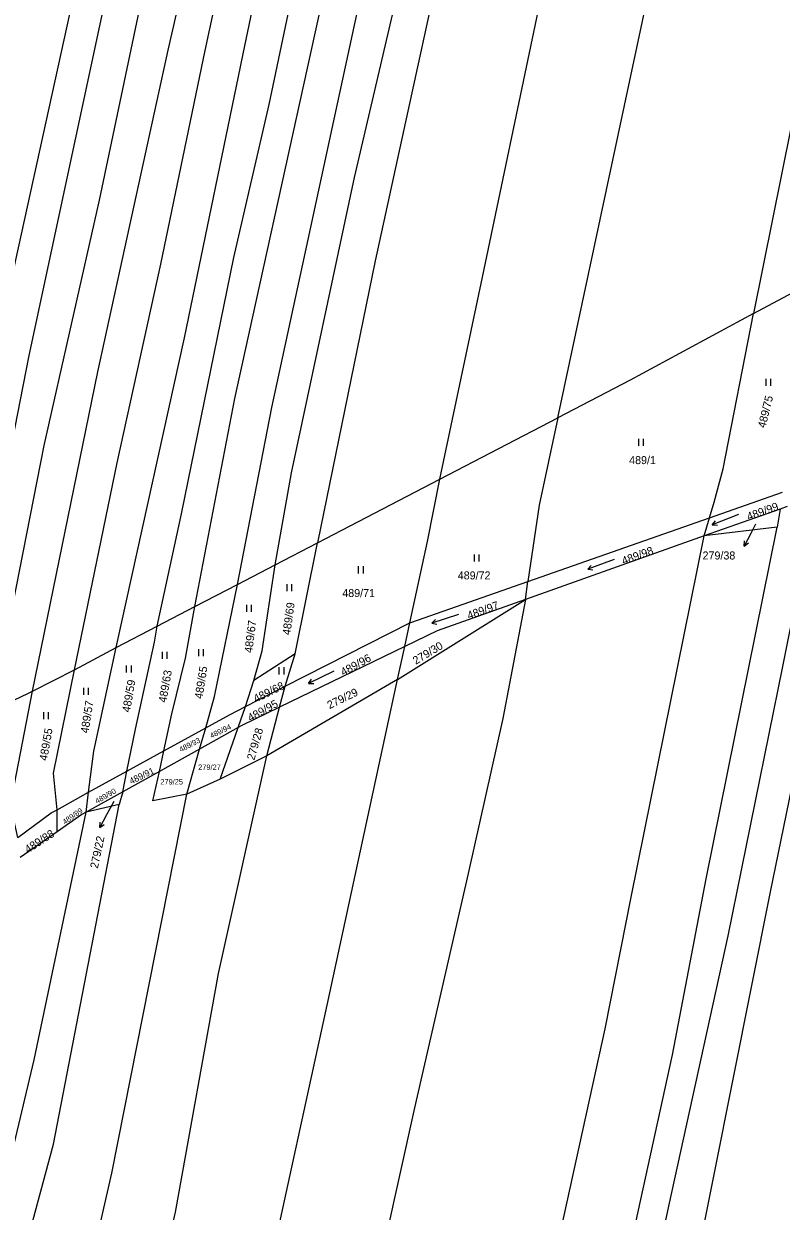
# Model space of a CAD drawing. Extents: x -776734 to -748832, y -1118122 to -976986.
# Drawn here: x -753584.3 to -753423.3, y -1114445.3 to -1114193.1 of the extents above; entities that cross this region are included whole.
import ezdxf

# ---------------------------------------------------------------- set-up
doc = ezdxf.new("R2010")
doc.units = 0
for name, color, linetype in [('KM_Hranice parcel', 7, 'Continuous'), ('KM_Parcelní čísla', 7, 'Continuous'), ('KM_Pop  PČ popisy', 7, 'Continuous'), ('KM_Značky kultur', 7, 'Continuous')]:
    doc.layers.add(name, color=color, linetype=linetype)

msp = doc.modelspace()

# ---------------------------------------------------------------- linework, layer by layer
at = {"layer": 'KM_Hranice parcel'}
for p, q in [((-753429.17, -1114254.65), (-753413.34, -1114246.13)), ((-753495.84, -1114289.8), (-753470.77, -1114276.76)), ((-753521.82, -1114303.32), (-753495.84, -1114289.8)), ((-753438.54, -1114298.02), (-753423.06, -1114292.6)), ((-753423.53, -1114296.17), (-753439.66, -1114301.88)), ((-753423.53, -1114296.17), (-753424.14, -1114300.03)), ((-753422.06, -1114295.65), (-753423.53, -1114296.17)), ((-753477.13, -1114311.53), (-753438.54, -1114298.02)), ((-753439.66, -1114301.88), (-753438.54, -1114298.02)), ((-753439.66, -1114301.88), (-753477.67, -1114315.36)), ((-753424.14, -1114300.03), (-753439.66, -1114301.88)), ((-753530.86, -1114308.02), (-753521.82, -1114303.32)), ((-753526.58, -1114326.91), (-753521.82, -1114303.32)), ((-753538.85, -1114312.17), (-753530.86, -1114308.02)), ((-753547.91, -1114316.89), (-753538.85, -1114312.17)), ((-753477.67, -1114315.36), (-753477.13, -1114311.53)), ((-753555.9, -1114321.04), (-753547.91, -1114316.89)), ((-753504.85, -1114332.37), (-753477.67, -1114315.36)), ((-753564.61, -1114325.57), (-753555.9, -1114321.04)), ((-753528.69, -1114333.8), (-753502.23, -1114320.34)), ((-753503.32, -1114325.36), (-753502.23, -1114320.34)), ((-753573.52, -1114330.35), (-753564.61, -1114325.57)), ((-753526.58, -1114326.91), (-753535.38, -1114332.61)), ((-753503.32, -1114325.36), (-753529.95, -1114338.28)), ((-753528.69, -1114333.8), (-753526.58, -1114326.91)), ((-753504.85, -1114332.37), (-753503.32, -1114325.36)), ((-753582.4, -1114334.83), (-753573.52, -1114330.35)), ((-753504.85, -1114332.37), (-753532.61, -1114348.57)), ((-753537.14, -1114338.1), (-753535.38, -1114332.61)), ((-753537.14, -1114338.1), (-753528.69, -1114333.8)), ((-753529.95, -1114338.28), (-753528.69, -1114333.8)), ((-753538.7, -1114342.58), (-753537.14, -1114338.1)), ((-753532.61, -1114348.57), (-753529.95, -1114338.28)), ((-753554.5, -1114347.52), (-753545.6, -1114342.62)), ((-753538.7, -1114342.58), (-753546.89, -1114347.14)), ((-753546.89, -1114347.14), (-753545.6, -1114342.62)), ((-753542.51, -1114353.54), (-753538.7, -1114342.58)), ((-753562.35, -1114351.85), (-753554.5, -1114347.52)), ((-753546.89, -1114347.14), (-753555.45, -1114351.91)), ((-753555.45, -1114351.91), (-753554.5, -1114347.52)), ((-753549.64, -1114356.75), (-753546.89, -1114347.14)), ((-753532.61, -1114348.57), (-753542.51, -1114353.54)), ((-753570.49, -1114356.33), (-753562.35, -1114351.85)), ((-753563.25, -1114356.26), (-753562.35, -1114351.85)), ((-753555.45, -1114351.91), (-753563.25, -1114356.26)), ((-753542.51, -1114353.54), (-753549.64, -1114356.75)), ((-753577.2, -1114360.03), (-753570.49, -1114356.33)), ((-753563.25, -1114356.26), (-753571.04, -1114360.59)), ((-753571.04, -1114360.59), (-753570.49, -1114356.33)), ((-753563.25, -1114356.26), (-753564, -1114358.96)), ((-753577.2, -1114364.76), (-753577.2, -1114360.03)), ((-753564, -1114358.96), (-753571.04, -1114360.59)), ((-753577.2, -1114364.76), (-753585.03, -1114370.21))]:
    msp.add_line(p, q, dxfattribs=at)
for points in [[(-753608.19, -1114346.93), (-753596.36, -1114292.97), (-753586.03, -1114243.55), (-753569.78, -1114169.66), (-753560.35, -1114124.62), (-753547.57, -1114062.54), (-753533.68, -1113995.57), (-753524.07, -1113949.66), (-753513.98, -1113898.7), (-753506.88, -1113870.43)], [(-753598.73, -1114342.51), (-753594.36, -1114320.86), (-753583.17, -1114263.9), (-753562.71, -1114168.29), (-753555.72, -1114138), (-753551.03, -1114113.68), (-753544.65, -1114085.74), (-753532.01, -1114022.12), (-753520.94, -1113969.14), (-753514.09, -1113938.2), (-753501, -1113877.1)], [(-753591.07, -1114338.93), (-753579.95, -1114282.63), (-753568.14, -1114230.58), (-753557.64, -1114180.28), (-753544.14, -1114118.55), (-753532.02, -1114058.21), (-753520.81, -1114000.52), (-753514.59, -1113972.43), (-753508.16, -1113941.9), (-753499.59, -1113904.69), (-753494.06, -1113884.53)], [(-753582.4, -1114334.83), (-753568.51, -1114267.01), (-753553.58, -1114198.68), (-753543.84, -1114155.99), (-753535.58, -1114116.9), (-753521.24, -1114043.89), (-753516.98, -1114020.48), (-753510.32, -1113989.87), (-753503.63, -1113959.67), (-753488.52, -1113890.02)], [(-753573.52, -1114330.35), (-753564.39, -1114286.34), (-753555.14, -1114244.17), (-753545.74, -1114198.77), (-753535.91, -1114153.3), (-753520.71, -1114079.76), (-753511.5, -1114030.59), (-753499.97, -1113976.62), (-753481.82, -1113896.66)], [(-753564.61, -1114325.57), (-753550.12, -1114259.77), (-753537.29, -1114197.74), (-753523.27, -1114130.7), (-753511.38, -1114071.77), (-753496.6, -1113995.29), (-753484.67, -1113945.08), (-753475.94, -1113902.48)], [(-753555.9, -1114321.04), (-753550.73, -1114297.2), (-753539.65, -1114242.69), (-753532.15, -1114210.21), (-753521.99, -1114162.01), (-753520.84, -1114158.91), (-753510.57, -1114103.46), (-753502.17, -1114062.33), (-753490.56, -1114005.66), (-753475.57, -1113940.32), (-753469.41, -1113908.95)], [(-753547.91, -1114316.89), (-753539.44, -1114272.7), (-753520.11, -1114184.76), (-753509.22, -1114134.56), (-753498.77, -1114084.71), (-753488.88, -1114036.03), (-753482.9, -1114007.57), (-753474.46, -1113969.97), (-753468.16, -1113940.63), (-753466.95, -1113936.62), (-753463.04, -1113915.23)], [(-753538.85, -1114312.17), (-753531.54, -1114274.58), (-753498.78, -1114122.91), (-753484.27, -1114048.85), (-753472.42, -1113992.3), (-753462.34, -1113949.76), (-753457.43, -1113920.08)], [(-753530.86, -1114308.02), (-753527.38, -1114288.45), (-753514, -1114225.73), (-753501.6, -1114172.6), (-753490.07, -1114116.74), (-753479.62, -1114062.9), (-753470.71, -1114019.91), (-753462.85, -1113984.68), (-753453.22, -1113945.81), (-753449.22, -1113926.84)], [(-753442.96, -1113931.31), (-753445.42, -1113945.03), (-753450.94, -1113968.89), (-753464.78, -1114027.69), (-753475.54, -1114084.33), (-753487.65, -1114142.57), (-753494.88, -1114175.9), (-753509.56, -1114243.44), (-753521.82, -1114303.32)], [(-753495.84, -1114289.8), (-753486.79, -1114246.9), (-753475.23, -1114191.81), (-753464.4, -1114139.74), (-753451.98, -1114079.21), (-753441.77, -1114030.67), (-753429.61, -1113976.89), (-753424.88, -1113952.63), (-753423.66, -1113945.09)], [(-753470.77, -1114276.76), (-753441.12, -1114137.74), (-753424.35, -1114060.38), (-753413.47, -1114010.9), (-753402.98, -1113955.94)], [(-753369.06, -1113973.07), (-753377.15, -1114013.76), (-753383.34, -1114043.87), (-753402.51, -1114123.4), (-753419.13, -1114204.72), (-753429.17, -1114254.65)], [(-753429.17, -1114254.65), (-753455.43, -1114268.78), (-753470.77, -1114276.76)], [(-753438.54, -1114298.02), (-753437.58, -1114294.72), (-753435.65, -1114287.64), (-753429.17, -1114254.65)], [(-753470.77, -1114276.76), (-753474.75, -1114295.34), (-753477.13, -1114311.53)], [(-753514.21, -1114792.57), (-753503.61, -1114744.79), (-753488.31, -1114675.57), (-753468.49, -1114582.84), (-753445.47, -1114477.34), (-753425.56, -1114377.48), (-753408.97, -1114296.71), (-753408.09, -1114290.87)], [(-753502.23, -1114320.34), (-753498.47, -1114303.05), (-753495.84, -1114289.8)], [(-753521.92, -1114790.76), (-753514.51, -1114760.97), (-753506.94, -1114724.35), (-753491.12, -1114648.31), (-753472.33, -1114560.66), (-753460.31, -1114505.63), (-753447.2, -1114444.23), (-753434.61, -1114386.82), (-753422.98, -1114329.63), (-753416.75, -1114298.6), (-753415.43, -1114293.38)], [(-753545.64, -1114785.18), (-753539.64, -1114765.18), (-753534.46, -1114742.36), (-753520.67, -1114684.28), (-753515.99, -1114660.95), (-753492.74, -1114552.19), (-753480.23, -1114495.22), (-753460.74, -1114406.56), (-753455.16, -1114378.63), (-753439.66, -1114301.88)], [(-753529.9, -1114788.88), (-753522.81, -1114764.12), (-753515.64, -1114728.13), (-753504, -1114672.45), (-753489.29, -1114604.59), (-753479.49, -1114562.47), (-753466.97, -1114506.52), (-753458.84, -1114469.04), (-753446.41, -1114412.13), (-753439.28, -1114374.74), (-753424.14, -1114300.03)], [(-753535.38, -1114332.61), (-753533.61, -1114326.29), (-753530.86, -1114308.02)], [(-753545.6, -1114342.62), (-753543.71, -1114336), (-753538.85, -1114312.17)], [(-753502.23, -1114320.34), (-753502.03, -1114320.24), (-753477.13, -1114311.53)], [(-753477.67, -1114315.36), (-753482.48, -1114340.66), (-753489.85, -1114373.61), (-753501.24, -1114423.4), (-753519.79, -1114507.09), (-753533.42, -1114568.36), (-753549.84, -1114646.02), (-753557.48, -1114682.99), (-753569.89, -1114734.99)], [(-753554.5, -1114347.52), (-753552.8, -1114339.69), (-753549.92, -1114327.83), (-753547.91, -1114316.89)], [(-753477.67, -1114315.36), (-753496.43, -1114322.01), (-753503.32, -1114325.36)], [(-753562.35, -1114351.85), (-753560.54, -1114342.94), (-753556.48, -1114324.44), (-753555.9, -1114321.04)], [(-753570.49, -1114356.33), (-753569.38, -1114347.61), (-753564.61, -1114325.57)], [(-753577.2, -1114360.03), (-753577.98, -1114352.3), (-753573.52, -1114330.35)], [(-753577.47, -1114661.02), (-753560.15, -1114582.71), (-753549.26, -1114536.81), (-753532.61, -1114460.31), (-753519.8, -1114401.56), (-753504.85, -1114332.37)], [(-753591.07, -1114338.93), (-753583.28, -1114335.29), (-753582.4, -1114334.83)], [(-753585.51, -1114365.91), (-753587.1, -1114359.02), (-753582.4, -1114334.83)], [(-753545.6, -1114342.62), (-753540.58, -1114339.85), (-753537.14, -1114338.1)], [(-753529.95, -1114338.28), (-753537.93, -1114342.15), (-753538.7, -1114342.58)], [(-753592.44, -1114622.47), (-753574.91, -1114550.17), (-753567.53, -1114513.69), (-753552.03, -1114445.57), (-753542.86, -1114394.86), (-753532.61, -1114348.57)], [(-753549.64, -1114356.75), (-753556.81, -1114358.17), (-753555.45, -1114351.91)], [(-753603.16, -1114605.14), (-753593.5, -1114563.55), (-753577.95, -1114491.54), (-753565.52, -1114437.24), (-753549.64, -1114356.75)], [(-753614.68, -1114589.42), (-753604.99, -1114548.2), (-753599.07, -1114517.95), (-753588.73, -1114471.06), (-753577.95, -1114431.09), (-753564, -1114358.96)], [(-753585.51, -1114365.91), (-753578.48, -1114360.73), (-753577.2, -1114360.03)], [(-753619.81, -1114582.42), (-753609.4, -1114537.29), (-753605.28, -1114514.09), (-753591.27, -1114451.72), (-753582.07, -1114413.16), (-753571.04, -1114360.59)], [(-753571.04, -1114360.59), (-753571.91, -1114361.08), (-753577.2, -1114364.76)]]:
    msp.add_lwpolyline(points, dxfattribs=at)
at = {"layer": 'KM_Pop  PČ popisy'}
for p, q in [((-753428.79, -1114299.37), (-753429.78, -1114301.35)), ((-753429.78, -1114301.35), (-753431.142, -1114304.024)), ((-753431.142, -1114304.024), (-753431.134, -1114302.904)), ((-753431.142, -1114304.024), (-753430.242, -1114303.359)), ((-753565.15, -1114358.27), (-753566.67, -1114361.16)), ((-753566.67, -1114361.16), (-753568.079, -1114363.81)), ((-753568.079, -1114363.81), (-753568.051, -1114362.69)), ((-753568.079, -1114363.81), (-753567.167, -1114363.161))]:
    msp.add_line(p, q, dxfattribs=at)
at = {"layer": 'KM_Značky kultur'}
for p, q in [((-753426.501, -1114269.97), (-753426.501, -1114268.47)), ((-753425.5, -1114269.97), (-753425.5, -1114268.47)), ((-753453.541, -1114282.77), (-753453.541, -1114281.27)), ((-753452.54, -1114282.77), (-753452.54, -1114281.27)), ((-753432.368, -1114297.353), (-753437.97, -1114299.503)), ((-753437.97, -1114299.503), (-753437.237, -1114298.685)), ((-753437.97, -1114299.503), (-753436.878, -1114299.621)), ((-753488.501, -1114307.32), (-753488.501, -1114305.82)), ((-753487.5, -1114307.32), (-753487.5, -1114305.82)), ((-753458.78, -1114306.882), (-753464.418, -1114308.934)), ((-753513.101, -1114309.83), (-753513.101, -1114308.33)), ((-753512.1, -1114309.83), (-753512.1, -1114308.33)), ((-753464.418, -1114308.934), (-753463.671, -1114308.128)), ((-753464.418, -1114308.934), (-753463.328, -1114309.071)), ((-753528.291, -1114313.63), (-753528.291, -1114312.13)), ((-753527.29, -1114313.63), (-753527.29, -1114312.13)), ((-753536.891, -1114317.98), (-753536.891, -1114316.48)), ((-753535.89, -1114317.98), (-753535.89, -1114316.48)), ((-753491.856, -1114318.58), (-753497.562, -1114320.434)), ((-753497.562, -1114320.434), (-753496.788, -1114319.655)), ((-753497.562, -1114320.434), (-753496.478, -1114320.609)), ((-753554.811, -1114327.99), (-753554.811, -1114326.49)), ((-753553.81, -1114327.99), (-753553.81, -1114326.49)), ((-753547.071, -1114327.43), (-753547.071, -1114325.93)), ((-753546.07, -1114327.43), (-753546.07, -1114325.93)), ((-753562.411, -1114330.9), (-753562.411, -1114329.4)), ((-753561.41, -1114330.9), (-753561.41, -1114329.4)), ((-753529.961, -1114331.29), (-753529.961, -1114329.79)), ((-753528.96, -1114331.29), (-753528.96, -1114329.79)), ((-753518.363, -1114330.575), (-753523.756, -1114333.205)), ((-753523.756, -1114333.205), (-753523.097, -1114332.326)), ((-753571.491, -1114335.62), (-753571.491, -1114334.12)), ((-753570.49, -1114335.62), (-753570.49, -1114334.12)), ((-753523.756, -1114333.205), (-753522.657, -1114333.227)), ((-753579.991, -1114340.83), (-753579.991, -1114339.33)), ((-753578.99, -1114340.83), (-753578.99, -1114339.33))]:
    msp.add_line(p, q, dxfattribs=at)

# ---------------------------------------------------------------- texts
at = {"layer": 'KM_Parcelní čísla'}
for s, height, rotation, p in [('489/75', 1.7, 76, (-753426.685, -1114279.055)), ('489/99', 1.7, 20, (-753430.249, -1114298.648)), ('489/98', 1.7, 20, (-753456.829, -1114308.038)), ('489/69', 1.7, 82, (-753527.648, -1114323.008)), ('489/97', 1.7, 20, (-753489.679, -1114319.658)), ('489/67', 1.7, 83, (-753535.706, -1114326.793)), ('279/30', 1.7, 31, (-753500.962, -1114329.258)), ('489/96', 1.7, 29, (-753516.347, -1114331.703)), ('489/65', 1.7, 81, (-753546.31, -1114336.582)), ('489/63', 1.7, 80, (-753553.992, -1114337.377)), ('489/59', 1.7, 80, (-753561.712, -1114339.437)), ('489/68', 1.7, 26, (-753534.957, -1114337.323)), ('279/29', 1.7, 26, (-753519.297, -1114338.693)), ('489/57', 1.7, 81, (-753570.54, -1114343.882)), ('489/95', 1.7, 29, (-753536.117, -1114341.413)), ('489/94', 1.14, 26, (-753544.389, -1114344.922)), ('489/55', 1.7, 80, (-753579.322, -1114349.727)), ('489/93', 1.139, 27, (-753550.901, -1114347.847)), ('279/28', 1.7, 74, (-753535.282, -1114349.634)), ('489/91', 1.37, 26, (-753561.429, -1114354.68)), ('489/90', 1.14, 29.999997, (-753568.687, -1114358.817)), ('489/89', 1.14, 35, (-753575.551, -1114363.255)), ('489/88', 1.7, 33, (-753583.397, -1114369.352)), ('279/22', 1.7, 78, (-753568.534, -1114372.635))]:
    msp.add_text(s, height=height, rotation=rotation, dxfattribs=at).set_placement(p)
for s, height, p in [('489/1', 1.7, (-753455.62, -1114286.62)), ('279/38', 1.7, (-753440.015, -1114306.878)), ('489/72', 1.7, (-753492.04, -1114311.11)), ('489/71', 1.7, (-753516.58, -1114314.86)), ('279/27', 1.14, (-753547.207, -1114351.58)), ('279/25', 1.14, (-753555.247, -1114354.68))]:
    msp.add_text(s, height=height, dxfattribs=at).set_placement(p)

doc.saveas('drawing.dxf')
